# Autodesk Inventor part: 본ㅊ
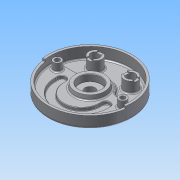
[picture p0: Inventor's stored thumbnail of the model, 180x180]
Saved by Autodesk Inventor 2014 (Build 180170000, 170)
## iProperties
Created: 2015-06
Part Number: 본ㅊ
Material: 알루미늄 6061
Document SubType Name: Modeling
Designer: Administrator
Density: 2.71 g/cm^3
Appearance: 알루미늄 - 평지
Mass: 1070.94 g
Surface Area: 1034.54 cm^2
Volume: 395.182 cm^3
Author: Administrator
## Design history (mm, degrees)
sketch "스케치1"
  geometry: C1 r 95 at (0, 0); 1 further point
  constraints: 1 centre point, 1 coincident
  dimensions: "d0" = 190 diameter of C1
extrude "돌출1" new body sketch "스케치1" distance "d1" = 32; taper "d2" = 0 deg
sketch "스케치2"
  geometry: C1 r 95 at (0, 0) reference; C2 r 90 at (0, 0)
  constraints: 1 centre point, 1 coincident
  dimensions: "d7" = 180 diameter of C2
extrude "돌출2" cut sketch "스케치2" distance "d8" = 18; taper "d9" = 0 deg
sketch "스케치4"
  geometry: L1 (-88.566, 16)-(-38.833, 16); L2 (38.833, 16)-(88.566, 16); A1 r 90 centre (0, 0) between (88.566, 16) and (-88.566, 16) reference; A2 r 42 centre (0, 0) between (-38.833, 16) and (38.833, 16); 1 further point
  constraints: 4 end point, 4 point on circle, 2 horizontal, 1 centre point, 1 coincident, 1 vertical alignment
  dimensions: "d12" = 84 diameter of A2; "d14" = 16 distance of A1.centre point (0, 16); "d15" = 38.83298 distance of point (0, 16) L1.end; "d16" = 38.83298 distance of L2.start point (0, 16)
extrude "돌출4" cut sketch "스케치4" distance "d19" = 7; taper "d20" = 0 deg
sketch "스케치5"
  geometry: L1 (0, 0)-(95, 0); L2 (0, 0)-(-95, 0); L3 (0, 0)-(-94.075, -13.221); L4 (0, 0)-(94.075, -13.221); A1 r 95 centre (0, 0) between (95, 0) and (-95, 0) reference
  constraints: 8 end point, 4 point on circle, 1 collinear, 1 horizontal
  dimensions: "d21" = 8 deg angle of L3 L2; "d22" = 8 deg angle of L4 L1
extrude "돌출5" cut sketch "스케치5" distance "d23" = 5; taper "d24" = 0 deg
sketch "스케치6"
  geometry: C1 r 15 at (-40, 52); C2 r 15 at (40, 52); A1 r 90 centre (0, 0) between (88.566, 16) and (-88.566, 16) reference
  constraints: 2 centre point, 1 equal radius, 1 horizontal alignment
  dimensions: "d25" = 52 vertical distance of A1.centre C2.centre; "d26" = 30 diameter of C1; "d27" = 40 horizontal distance of A1.centre C1.centre; "d28" = 40 horizontal distance of C2.centre A1.centre
extrude "돌출6" join sketch "스케치6" distance "d29" = 25; taper "d30" = 0 deg
hole "구멍1" diameter "d33" = 20; stored, may be unused: countersink angle "d37" = 90 deg, drill point angle "d39" = 118 deg; dims "d31" = 10, "d32" = 10, "d34" = 6, "d35" = 4, "d36" = 2, "d38" = 8
hole "구멍2" diameter "d42" = 20; stored, may be unused: countersink angle "d46" = 90 deg, drill point angle "d48" = 118 deg; dims "d40" = 10, "d41" = 10, "d43" = 6, "d44" = 4, "d45" = 2, "d47" = 8
sketch "스케치7"
  geometry: L1 (-6, 20.367)-(6, 20.367); L2 (6, 20.367)-(6, -20.367); L3 (6, -20.367)-(-6, -20.367); L4 (-6, -20.367)-(-6, 20.367); L5 (-6, 20.367)-(6, -20.367); L6 (6, 20.367)-(-6, -20.367); L7 (58.462, 6)-(101.538, 6); L8 (101.538, 6)-(101.538, -6); L9 (101.538, -6)-(58.462, -6); L10 (58.462, -6)-(58.462, 6); L11 (58.462, 6)-(101.538, -6); L12 (101.538, 6)-(58.462, -6); C1 r 15 at (0, 0) reference; C2 r 15 at (80, 0) reference; 1 further point
  constraints: 24 end point, 4 midpoint, 4 parallel, 2 horizontal, 2 perpendicular
  dimensions: "d49" = 12 distance of L1.start L1.end; "d50" = 12 distance of L7.end L8.end; "d51" = 43.07513 distance between parallel lines of L8 L10; "d52" = 40.7331 distance between parallel lines of L3 L1
extrude "돌출7" cut sketch "스케치7" distance "d53" = 3; taper "d54" = 0 deg
sketch "스케치8"
  geometry: C1 r 35 at (0, 0); A1 r 90 centre (0, 0) between (-88.566, 16) and (88.566, 16) reference
  constraints: 1 centre point, 1 coincident
  dimensions: "d55" = 70 diameter of C1
extrude "돌출8" join sketch "스케치8" distance "d56" = 10; taper "d57" = -10 deg
sketch "스케치9"
  geometry: C1 r 95 at (0, 0) reference; C2 r 26 at (0, 0)
  constraints: 1 centre point, 1 coincident
  dimensions: "d58" = 52 diameter of C2
extrude "돌출9" join sketch "스케치9" distance "d59" = 12; taper "d60" = -15 deg
hole "구멍3" diameter "d63" = 23; stored, may be unused: countersink angle "d67" = 90 deg, drill point angle "d69" = 118 deg; dims "d61" = 10, "d62" = 10, "d64" = 6, "d65" = 50, "d66" = 15, "d68" = 8
sketch "스케치10"
  geometry: L1 (-59, -19)-(-59, -14); L2 (-41, -19)-(-41, -14); L3 (41, -19)-(41, -14); L4 (59, -19)-(59, -14); L5 (41, -14)-(59, -14); L6 (-41, -14)-(-59, -14); C1 r 35 at (0, 0) reference; A1 r 41 centre (0, -19) between (-41, -19) and (41, -19); A2 r 59 centre (0, -19) between (-59, -19) and (59, -19); 5 further points
  constraints: 12 end point, 4 perpendicular, 4 point on circle, 4 tangent, 2 centre point, 2 coincident, 2 horizontal alignment, 2 midpoint, 2 vertical alignment, 1 parallel, 4 other
  dimensions: "d73" = 59 radius of A2; "d74" = 41 radius of A1; "d76" = 19 distance of C1.centre A2.centre; "d77" = 14 distance of C1.centre point (0, -14); "d78" = 14 distance from line of C1.centre L6; "d79" = 0 distance between parallel lines of L6 L5; "d80" = 29.56636 distance from line of point (88.566, 16) L4
extrude "돌출10" cut sketch "스케치10" distance "d81" = 7; taper "d82" = 0 deg
sketch "스케치11"
  geometry: C1 r 35 at (0, 0) reference; C2 r 9 at (-74, 0); C3 r 9 at (74, 0); A1 r 42 centre (0, 0) between (38.833, 16) and (-38.833, 16) reference; A2 r 15 centre (-40, 52) between (-46, 65.748) and (-46, 38.252) reference; A3 r 15 centre (40, 52) between (53.748, 58) and (26.252, 58) reference
  constraints: 2 centre point, 1 equal radius
  dimensions: "d83" = 18 diameter of C2; "d84" = 52 vertical distance of C2.centre A2.centre; "d85" = 52 vertical distance of C3.centre A3.centre; "d86" = 74 distance of A1.centre C2.centre; "d87" = 74 distance of C3.centre C1.centre
extrude "돌출11" join sketch "스케치11" distance "d88" = 18; taper "d89" = 0 deg
sketch "스케치12"
  geometry: C1 r 9 at (-74, 0) reference; C2 r 9 at (74, 0) reference; 2 further points
  constraints: 2 coincident
hole "구멍4" sketch "스케치12" at (-74, 0), (74, 0) diameter "d90" = 11; stored, may be unused: countersink angle "d94" = 90 deg, drill point angle "d96" = 118 deg; dims "d91" = 6, "d92" = 18, "d93" = 11, "d95" = 8
sketch "스케치13"
  geometry: C1 r 95 at (0, 0) reference; C2 r 68 at (0, 0)
  constraints: 1 centre point, 1 coincident, 1 other
  dimensions: "d97" = 136 diameter of C2
feature "엠보싱1" sketch "스케치13" dims "d1" = 32, "d98" = 0.5, "d99" = 0
fillet "모깎기1" dims "d100" = 10
fillet "모깎기2" dims "d101" = 0.3
fillet "모깎기3" dims "d102" = 5
fillet "모깎기4" dims "d103" = 1
chamfer "모따기1" distance "d104" = 1; stored, may be unused: second distance "d105" = 2, angle "d106" = 45 deg
fillet "모깎기5" dims "d107" = 3
chamfer "모따기2" distance "d110" = 1; stored, may be unused: second distance "d111" = 2, angle "d112" = 45 deg
fillet "모깎기8" dims "d113" = 3
fillet "모깎기9" dims "d114" = 3
fillet "모깎기10" dims "d115" = 3
fillet "모깎기11" dims "d116" = 3
node "솔리드1"
other parameters: "d71" = 59, "d72" = 41
